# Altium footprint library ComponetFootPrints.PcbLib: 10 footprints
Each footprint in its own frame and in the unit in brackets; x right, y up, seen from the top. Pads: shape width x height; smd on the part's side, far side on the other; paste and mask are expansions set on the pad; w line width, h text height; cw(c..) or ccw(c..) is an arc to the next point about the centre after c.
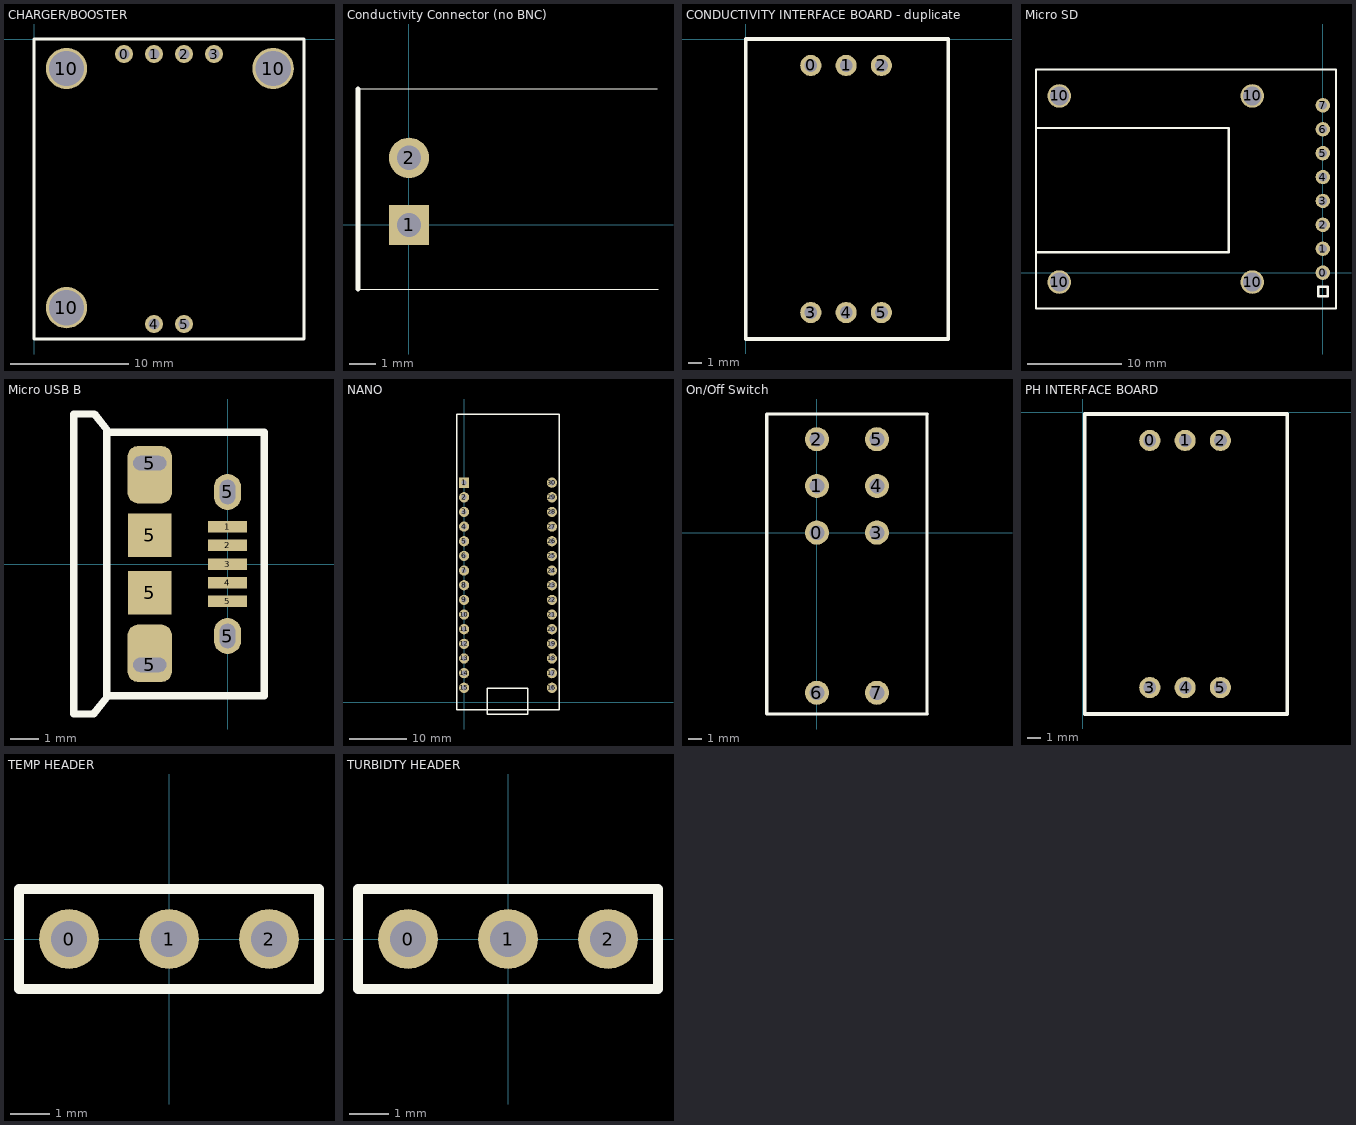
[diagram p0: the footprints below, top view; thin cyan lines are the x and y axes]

## CHARGER/BOOSTER [mm]
pads (9):
  round 1.524 hole 0.914: 0(7.62,-1.27) 1(10.16,-1.27) 2(12.7,-1.27) 3(15.24,-1.27) 4(10.16,-24.13) 5(12.7,-24.13)
  round 3.5 hole 3: 10(2.75,-22.75) 10(2.75,-2.5) 10(20.25,-2.5)
Top Overlay:
  lines w0.254: 0,-25.4 22.86,-25.4 22.86,0 0,0 0,-25.4
3D body: height 11, standoff 10, extent 0.127,-25.273 22.733,-0.127
3D body: height 10, standoff 0, extent 6.55,-2.3 16.4,-0.3
3D body: height 10, standoff 0, extent 9.1,-25.15 13.85,-23.15

## Conductivity Connector (no BNC) [mm]
pads (2):
  rect 1.5x1.5 hole 0.9: 1(0.005,-0.014)
  round 1.5 hole 0.9: 2(0.005,2.486)
Top Overlay:
  lines w0.025: 9.242,5.05 -1.895,5.05 -1.895,-2.4 9.276,-2.4
  lines w0.2: -1.895,-2.4 -1.895,5.05

## CONDUCTIVITY INTERFACE BOARD - duplicate [mil]
pads (6):
  round 60 hole 35.98: 0(185,-75) 1(285,-75) 2(385,-75) 3(185,-775) 4(285,-775) 5(385,-775)
Top Overlay:
  lines w10: 0,-850 0,0 575,0 575,-850 0,-850
3D body: height 393.7, standoff 0, extent 141.73,-814.96 429.13,-736.22
3D body: height 393.7, standoff 0, extent 141.73,-114.17 429.13,-35.43
3D body: height 433.07, standoff 393.7, extent 5,-845 570,-5

## Micro SD [mm]
pads (12):
  round 1.524 hole 0.914: 0(0,0) 1(0,2.54) 2(0,5.08) 3(0,7.62) 4(0,10.16) 5(0,12.7) 6(0,15.24) 7(0,17.78)
  round 2.5 hole 2 unplated: 10(-28,-1) 10(-28,18.78) 10(-7.5,-1) 10(-7.5,18.78)
Top Overlay:
  lines w0.254: -30.48,2.159 -10,2.159 -10,15.367 -30.48,15.367 ; -30.48,-3.81 1.397,-3.81 1.397,21.59 -30.48,21.59 -30.48,-3.81 ; -0.5,-2.5 -0.5,-1.5 0.5,-1.5 0.5,-2.5 -0.5,-2.5
3D body: height 10, standoff 0, extent -8.975,17.4 -6.025,20.2
3D body: height 10, standoff 0, extent -29.475,-2.35 -26.525,0.45
3D body: height 10, standoff 0, extent -29.425,17.35 -26.475,20.15
3D body: height 10, standoff 0, extent -9.025,-2.35 -6.075,0.45
3D body: height 10, standoff 0, extent -0.95,-1.275 1.05,18.95
3D body: height 11, standoff 10, extent -30.48,-3.81 1.397,21.59

## Micro USB B [mm]
pads (11):
  rect 1.35x0.4 smd: 1(0,1.3) 2(0,0.65) 3(0,-0.015) 4(0,-0.65) 5(0,-1.3)
  rrect50% 1.55x2 hole 0.5 slot 1.15 at 0 deg copper offset 0,0.4: 5(-2.7,-3.5)
  rect 1.5x1.5 smd: 5(-2.7,-1) 5(-2.7,1)
  rrect50% 1.55x2 hole 0.5 slot 1.15 at 0 deg copper offset 0,-0.4: 5(-2.7,3.5)
  oval 0.95x1.25 hole 0.55 slot 0.85 at 90 deg: 5(0,-2.5) 5(0,2.5)
Top Overlay:
  lines w0.254: -4.191,-4.572 1.27,-4.572 1.27,4.572 -4.191,4.572 ; -5.334,-5.207 -5.334,5.207 -4.623,5.207 -4.191,4.667 -4.191,-4.635 -4.648,-5.207 -5.334,-5.207

## NANO [mil]
pads (30):
  rect 70x70 hole 36: 1(0,1500)
  round 70 hole 36: 2(0,1400) 3(0,1300) 4(0,1200) 5(0,1100) 6(0,1000) 7(0,900) 8(0,800) 9(0,700) 10(0,600) 11(0,500) 12(0,400) 13(0,300) 14(0,200) 15(0,100) 16(600,100) 17(600,200) 18(600,300) 19(600,400) 20(600,500) 21(600,600) 22(600,700) 23(600,800) 24(600,900) 25(600,1000) 26(600,1100) 27(600,1200) 28(600,1300) 29(600,1400) 30(600,1500)
Top Overlay:
  lines w10: -50,-50 -50,1968.5 650,1968.5 650,-50 -50,-50 ; 157.48,-78.74 157.48,98.43 433.07,98.43 433.07,-78.74 157.48,-78.74
3D body: height 551.18, standoff 472.44, extent 472.44,1692.91 590.55,1909.45
3D body: height 551.18, standoff 472.44, extent 39.37,1692.91 98.43,1929.13
3D body: height 551.18, standoff 472.44, extent 157.48,-78.74 433.07,98.43
3D body: height 433.07, standoff 393.7, extent -50,-50 650,1968.5
3D body: height 393.7, standoff 0, extent -39.37,59.06 39.37,1555.12
3D body: height 393.7, standoff 0, extent 560,53.94 638.74,1550

## On/Off Switch [mm] "DPDT toggle switch"
height 15
pads (8):
  round 1.8 hole 1.1: 0(0,0) 1(0,3.5) 2(0,7) 3(4.5,0) 4(4.5,3.5) 5(4.5,7) 6(0,-12) 7(4.5,-12)
Top Overlay:
  lines w0.254: 8.25,-13.589 8.25,8.89 ; 8.255,-13.589 -3.75,-13.589 -3.75,8.89 8.255,8.89

## PH INTERFACE BOARD [mil]
pads (6):
  round 60 hole 35.98: 0(190,-80) 1(290,-80) 2(390,-80) 3(190,-780) 4(290,-780) 5(390,-780)
Top Overlay:
  lines w10: 5,-855 5,-5 580,-5 580,-855 5,-855
3D body: height 393.7, standoff 0, extent 146.3,-819.37 433.7,-740.62
3D body: height 393.7, standoff 0, extent 147.64,-120.08 435.04,-41.33
3D body: height 433.07, standoff 393.7, extent 10,-850 575,-10

## TEMP HEADER [mil]
pads (3):
  round 60 hole 35.98: 0(-100,0) 1(0,0) 2(100,0)
Top Overlay:
  lines w10: -150,-50 150,-50 150,50 -150,50 -150,-50
3D body: height 393.7, standoff 0, extent -143.7,-39.37 143.7,39.37
3D body: height 433.07, standoff 393.7, extent -145,-45 145,45

## TURBIDTY HEADER [mil]
pads (3):
  round 60 hole 35.98: 0(-100,0) 1(0,0) 2(100,0)
Top Overlay:
  lines w10: -150,-50 150,-50 150,50 -150,50 -150,-50
3D body: height 393.7, standoff 0, extent -143.7,-39.37 143.7,39.37
3D body: height 433.07, standoff 393.7, extent -145,-45 145,45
